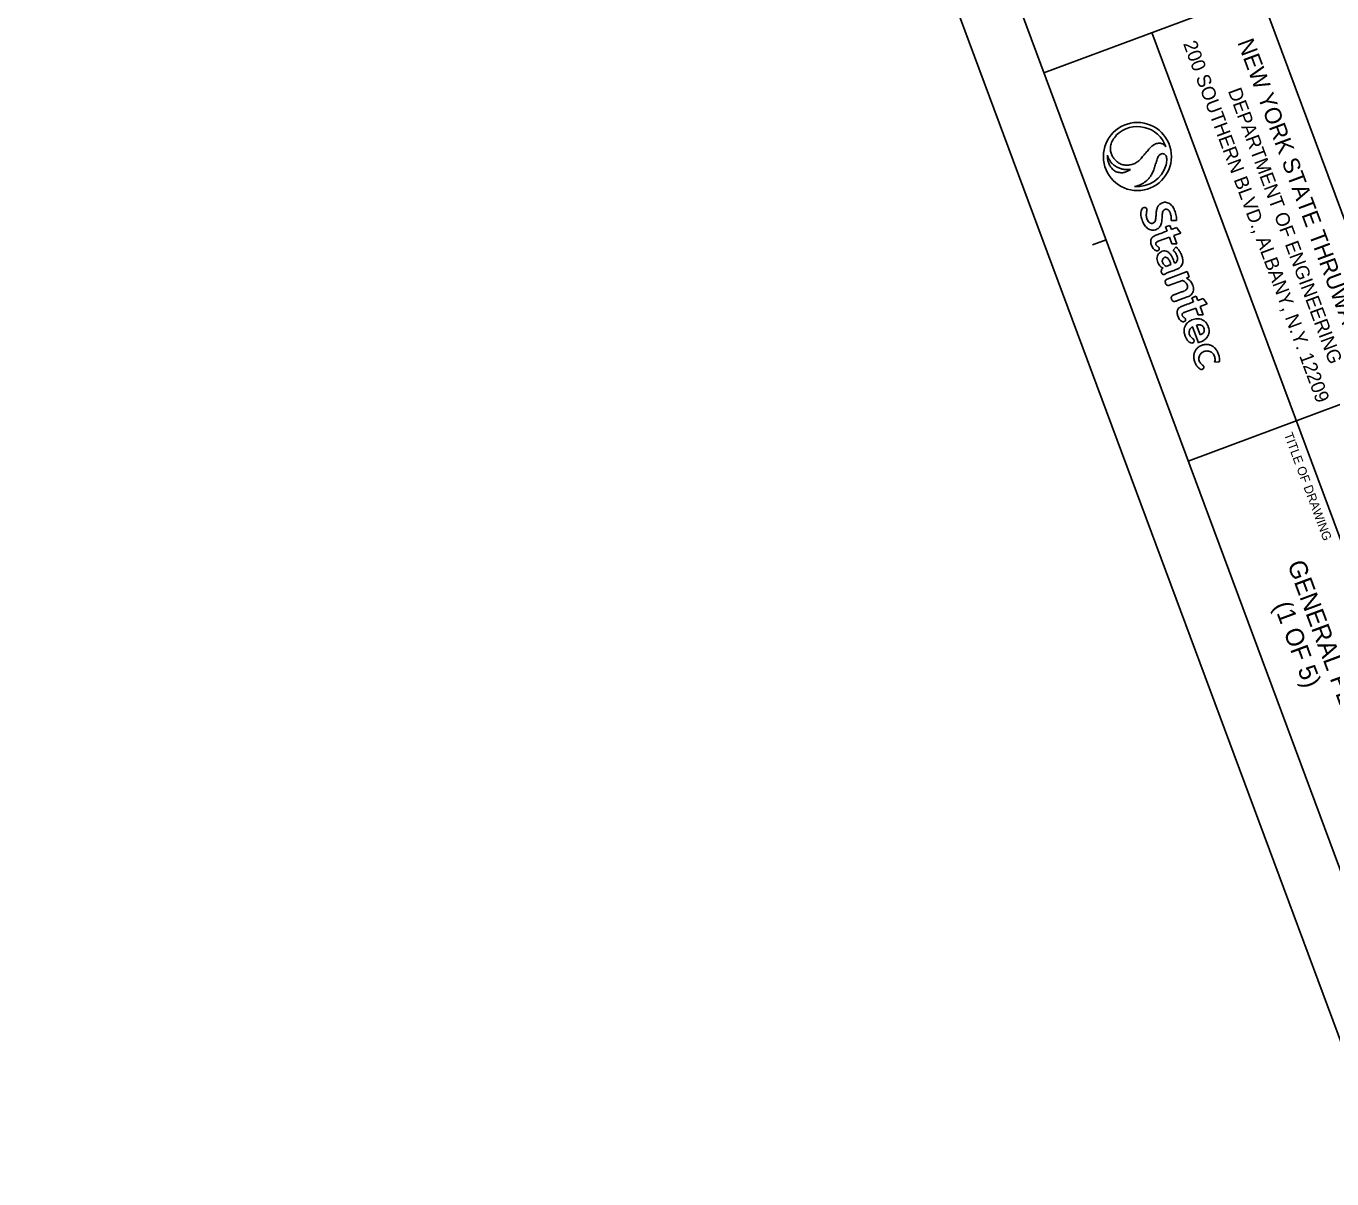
# Model space of a CAD drawing. Extents: x 1040172 to 1040822, y 1127790 to 1128580.
# Drawn here: x 1040172.1 to 1040398.7, y 1127789.6 to 1127989.6 of the extents above; entities that cross this region are included whole.
import ezdxf

# ---------------------------------------------------------------- set-up
doc = ezdxf.new("R2010")
doc.units = 0
for name, color, linetype in [('clip boundary', 7, 'Continuous'), ('G-ANNO-LOGO', 7, 'Continuous'), ('O_Details_Text Title and Subtitle Proposed_P_T', 7, 'Continuous'), ('SHEET_BORDER', 7, 'Continuous'), ('SHEET_BORDER_CUT', 7, 'Continuous')]:
    doc.layers.add(name, color=color, linetype=linetype)

msp = doc.modelspace()

# ---------------------------------------------------------------- linework, layer by layer
at = {"layer": 'clip boundary'}
msp.add_lwpolyline([(1040584.48, 1128580.33), (1040821.52, 1127942.99), (1040409.12, 1127789.61), (1040172.08, 1128426.95)], close=True, dxfattribs=at)
at = {"layer": 'G-ANNO-LOGO'}
for p, q in [((1040370.61, 1127955.06), (1040369.85, 1127954.78)), ((1040369.85, 1127954.78), (1040370.11, 1127954.08)), ((1040370.87, 1127954.37), (1040370.61, 1127955.06)), ((1040370.85, 1127955.9), (1040371.72, 1127955.92)), ((1040371.77, 1127954.7), (1040370.87, 1127954.37)), ((1040372.48, 1127953.73), (1040371.77, 1127954.7)), ((1040368.59, 1127952.3), (1040370.51, 1127953)), ((1040370.51, 1127953), (1040370.94, 1127951.85)), ((1040371.27, 1127953.28), (1040372.48, 1127953.73)), ((1040371.8, 1127951.87), (1040371.27, 1127953.28)), ((1040370.94, 1127951.85), (1040371.8, 1127951.87)), ((1040371.69, 1127951.31), (1040371.17, 1127950.74)), ((1040370.79, 1127948.27), (1040369.93, 1127947.95)), ((1040373.6, 1127947.03), (1040370.12, 1127945.74)), ((1040370.52, 1127944.67), (1040372.81, 1127945.52)), ((1040373.5, 1127945.88), (1040373.94, 1127946.11)), ((1040373.94, 1127946.11), (1040373.6, 1127947.03)), ((1040375.19, 1127942.75), (1040374.43, 1127942.47)), ((1040374.43, 1127942.47), (1040374.69, 1127941.77)), ((1040375.45, 1127942.05), (1040375.19, 1127942.75)), ((1040376.35, 1127942.39), (1040375.45, 1127942.05)), ((1040375.85, 1127940.97), (1040377.06, 1127941.42)), ((1040376.38, 1127939.56), (1040375.85, 1127940.97)), ((1040377.06, 1127941.42), (1040376.35, 1127942.39)), ((1040373.17, 1127939.99), (1040375.09, 1127940.69)), ((1040375.09, 1127940.69), (1040375.52, 1127939.54)), ((1040375.52, 1127939.54), (1040376.38, 1127939.56)), ((1040374.55, 1127937.47), (1040375.58, 1127934.7)), ((1040375.84, 1127936.05), (1040375.22, 1127937.72)), ((1040378.36, 1127931.34), (1040379.16, 1127931.37))]:
    msp.add_line(p, q, dxfattribs=at)
for points in [[(1040369.88, 1127968.71), (1040369.88, 1127968.71)], [(1040369.97, 1127965.55), (1040369.96, 1127965.55)]]:
    msp.add_lwpolyline(points, dxfattribs=at)
msp.add_circle((1040364.96, 1127967), 5.91, dxfattribs=at)
for start, end in [(19.1677, 134.0856), (19.1612, 19.1677), (177.5195, 181.8591), (264.1826, 343.8337)]:
    msp.add_arc((1040364.96, 1127967), 5.21, start, end, dxfattribs=at)
for points, degree in [([(1040369.88, 1127968.71), (1040369.81, 1127968.82), (1040369.65, 1127969.07), (1040369.15, 1127969.3), (1040368.44, 1127969.34), (1040367.77, 1127969.05), (1040367.2, 1127968.56), (1040366.7, 1127967.96), (1040366.13, 1127967.32), (1040365.62, 1127966.66), (1040365.05, 1127966.12), (1040364.37, 1127965.7), (1040363.59, 1127965.52), (1040362.84, 1127965.48), (1040362.07, 1127965.67), (1040361.43, 1127966.06), (1040360.96, 1127966.53), (1040360.61, 1127966.99), (1040360.39, 1127967.57), (1040360.24, 1127968.24), (1040360.3, 1127968.98), (1040360.62, 1127969.87), (1040361.06, 1127970.4), (1040361.34, 1127970.74)], 3), ([(1040369.88, 1127968.71), (1040369.88, 1127968.71), (1040369.88, 1127968.71), (1040369.88, 1127968.71)], 2), ([(1040359.76, 1127967.22), (1040359.8, 1127967.1), (1040359.87, 1127966.81), (1040360.15, 1127966.36), (1040360.47, 1127965.86), (1040360.94, 1127965.48), (1040361.42, 1127965.15), (1040362.03, 1127964.9), (1040362.66, 1127964.74), (1040363.26, 1127964.71), (1040363.6, 1127964.76), (1040363.76, 1127964.78)], 3), ([(1040363.76, 1127964.78), (1040363.64, 1127964.7), (1040363.36, 1127964.49), (1040362.84, 1127964.27), (1040362.23, 1127964.15), (1040361.6, 1127964.25), (1040360.97, 1127964.47), (1040360.49, 1127964.95), (1040360.12, 1127965.51), (1040359.88, 1127966.14), (1040359.8, 1127966.61), (1040359.76, 1127966.83)], 3), ([(1040364.44, 1127961.82), (1040364.62, 1127961.84), (1040364.97, 1127961.89), (1040365.48, 1127962.09), (1040365.92, 1127962.31), (1040366.29, 1127962.6), (1040366.72, 1127962.94), (1040367.14, 1127963.41), (1040367.49, 1127963.99), (1040367.83, 1127964.7), (1040368.05, 1127965.51), (1040368.35, 1127966.37), (1040368.55, 1127967.05), (1040368.95, 1127967.41), (1040369.3, 1127967.54), (1040369.61, 1127967.46), (1040369.86, 1127967.29), (1040370.01, 1127966.99), (1040370.07, 1127966.59), (1040370.05, 1127966.1), (1040370, 1127965.74), (1040369.97, 1127965.55)], 3), ([(1040371.72, 1127955.92), (1040371.73, 1127955.97), (1040371.75, 1127956.23), (1040371.71, 1127956.68), (1040371.58, 1127957.21), (1040371.43, 1127957.67), (1040371.25, 1127958.04), (1040371.04, 1127958.38), (1040370.77, 1127958.68), (1040370.41, 1127958.93), (1040370.01, 1127959.06), (1040369.64, 1127959.08), (1040369.34, 1127959), (1040369.07, 1127958.89), (1040368.84, 1127958.73), (1040368.66, 1127958.54), (1040368.52, 1127958.34), (1040368.41, 1127958.11), (1040368.32, 1127957.85), (1040368.26, 1127957.55), (1040368.22, 1127957.19), (1040368.19, 1127956.8), (1040368.17, 1127956.4), (1040368.13, 1127956.07), (1040368.03, 1127955.79), (1040367.92, 1127955.59), (1040367.74, 1127955.46), (1040367.54, 1127955.4), (1040367.3, 1127955.4), (1040367.06, 1127955.51), (1040366.83, 1127955.74), (1040366.66, 1127956.06), (1040366.54, 1127956.43), (1040366.49, 1127956.78), (1040366.52, 1127957.09), (1040366.53, 1127957.34), (1040366.61, 1127957.53), (1040366.61, 1127957.69), (1040366.62, 1127957.83), (1040366.56, 1127957.96), (1040366.47, 1127958.08), (1040366.33, 1127958.16), (1040366.16, 1127958.18), (1040366, 1127958.13), (1040365.86, 1127958.05), (1040365.74, 1127957.87), (1040365.59, 1127957.55), (1040365.55, 1127957.07), (1040365.6, 1127956.51), (1040365.76, 1127955.99), (1040365.94, 1127955.55), (1040366.13, 1127955.18), (1040366.36, 1127954.88), (1040366.66, 1127954.58), (1040367.05, 1127954.34), (1040367.48, 1127954.2), (1040367.91, 1127954.24), (1040368.27, 1127954.35), (1040368.57, 1127954.51), (1040368.78, 1127954.74), (1040368.98, 1127954.98), (1040369.1, 1127955.33), (1040369.19, 1127955.7), (1040369.22, 1127956.09), (1040369.26, 1127956.51), (1040369.28, 1127956.95), (1040369.33, 1127957.33), (1040369.44, 1127957.61), (1040369.6, 1127957.77), (1040369.79, 1127957.86), (1040369.99, 1127957.87), (1040370.19, 1127957.81), (1040370.37, 1127957.68), (1040370.53, 1127957.49), (1040370.65, 1127957.22), (1040370.74, 1127956.96), (1040370.8, 1127956.68), (1040370.84, 1127956.4), (1040370.85, 1127956.14), (1040370.85, 1127955.97), (1040370.85, 1127955.9)], 3), ([(1040370.11, 1127954.08), (1040369.44, 1127953.83), (1040368.72, 1127953.57), (1040367.93, 1127953.26), (1040367.75, 1127953.16), (1040367.52, 1127952.98), (1040367.39, 1127952.77), (1040367.31, 1127952.57), (1040367.26, 1127952.37), (1040367.27, 1127952.08), (1040367.36, 1127951.72), (1040367.51, 1127951.37), (1040367.69, 1127951.03), (1040367.93, 1127950.8), (1040368.17, 1127950.66), (1040368.39, 1127950.64), (1040368.56, 1127950.69), (1040368.69, 1127950.77), (1040368.74, 1127950.87), (1040368.76, 1127950.98), (1040368.74, 1127951.09), (1040368.7, 1127951.2), (1040368.63, 1127951.3), (1040368.52, 1127951.36), (1040368.4, 1127951.44), (1040368.29, 1127951.56), (1040368.19, 1127951.68), (1040368.15, 1127951.84), (1040368.17, 1127951.99), (1040368.24, 1127952.13), (1040368.39, 1127952.23), (1040368.51, 1127952.28), (1040368.59, 1127952.3)], 3), ([(1040371.43, 1127948.51), (1040371.41, 1127948.58), (1040371.32, 1127948.81), (1040371.15, 1127949.19), (1040370.95, 1127949.65), (1040370.69, 1127950.06), (1040370.37, 1127950.4), (1040369.94, 1127950.64), (1040369.45, 1127950.65), (1040369.05, 1127950.47), (1040368.72, 1127950.28), (1040368.51, 1127949.96), (1040368.35, 1127949.55), (1040368.35, 1127949.05), (1040368.52, 1127948.59), (1040368.73, 1127948.19), (1040368.96, 1127947.91), (1040369.21, 1127947.74), (1040369.35, 1127947.68), (1040369.43, 1127947.64)], 3), ([(1040369.43, 1127947.64), (1040369.4, 1127947.62), (1040369.31, 1127947.58), (1040369.21, 1127947.44), (1040369.11, 1127947.26), (1040369.09, 1127946.99), (1040369.19, 1127946.75), (1040369.32, 1127946.54), (1040369.54, 1127946.52), (1040369.72, 1127946.58), (1040369.94, 1127946.72), (1040370.59, 1127947.03), (1040371.31, 1127947.24), (1040372.06, 1127947.54), (1040372.4, 1127947.77), (1040372.65, 1127948.1), (1040372.83, 1127948.41), (1040372.88, 1127948.85), (1040372.82, 1127949.35), (1040372.66, 1127949.9), (1040372.4, 1127950.43), (1040372.08, 1127950.91), (1040371.82, 1127951.18), (1040371.69, 1127951.31)], 3), ([(1040371.17, 1127950.74), (1040371.22, 1127950.7), (1040371.35, 1127950.58), (1040371.52, 1127950.36), (1040371.71, 1127950.09), (1040371.83, 1127949.82), (1040371.93, 1127949.52), (1040371.95, 1127949.22), (1040371.9, 1127948.94), (1040371.77, 1127948.71), (1040371.6, 1127948.57), (1040371.47, 1127948.52), (1040371.43, 1127948.51)], 3), ([(1040369.93, 1127947.95), (1040369.9, 1127947.97), (1040369.79, 1127948.04), (1040369.62, 1127948.19), (1040369.42, 1127948.4), (1040369.3, 1127948.67), (1040369.27, 1127948.93), (1040369.32, 1127949.14), (1040369.4, 1127949.3), (1040369.53, 1127949.42), (1040369.69, 1127949.5), (1040369.86, 1127949.53), (1040370.06, 1127949.49), (1040370.22, 1127949.36), (1040370.38, 1127949.19), (1040370.51, 1127948.94), (1040370.63, 1127948.68), (1040370.73, 1127948.44), (1040370.78, 1127948.32), (1040370.79, 1127948.27)], 3), ([(1040370.12, 1127945.74), (1040370.08, 1127945.71), (1040369.98, 1127945.65), (1040369.84, 1127945.51), (1040369.76, 1127945.26), (1040369.86, 1127944.98), (1040369.98, 1127944.72), (1040370.22, 1127944.62), (1040370.4, 1127944.62), (1040370.48, 1127944.66), (1040370.52, 1127944.67)], 3), ([(1040372.81, 1127945.52), (1040372.83, 1127945.51), (1040372.93, 1127945.46), (1040373.1, 1127945.32), (1040373.34, 1127945.15), (1040373.54, 1127944.89), (1040373.65, 1127944.59), (1040373.67, 1127944.27), (1040373.53, 1127943.99), (1040373.33, 1127943.79), (1040373.02, 1127943.62), (1040372.51, 1127943.47), (1040371.89, 1127943.21), (1040371.36, 1127943.05), (1040371, 1127942.89), (1040370.86, 1127942.69), (1040370.8, 1127942.43), (1040370.9, 1127942.18), (1040371.05, 1127941.96), (1040371.27, 1127941.82), (1040371.57, 1127941.86), (1040372.06, 1127942.1), (1040372.69, 1127942.3), (1040373.37, 1127942.57), (1040373.82, 1127942.7), (1040374.17, 1127942.9), (1040374.39, 1127943.12), (1040374.59, 1127943.41), (1040374.69, 1127943.79), (1040374.73, 1127944.24), (1040374.58, 1127944.68), (1040374.41, 1127945.06), (1040374.17, 1127945.37), (1040373.91, 1127945.63), (1040373.66, 1127945.77), (1040373.54, 1127945.85), (1040373.5, 1127945.88)], 3), ([(1040374.69, 1127941.77), (1040374.01, 1127941.52), (1040373.3, 1127941.25), (1040372.51, 1127940.95), (1040372.33, 1127940.84), (1040372.09, 1127940.67), (1040371.97, 1127940.46), (1040371.89, 1127940.26), (1040371.84, 1127940.06), (1040371.85, 1127939.77), (1040371.94, 1127939.41), (1040372.09, 1127939.06), (1040372.27, 1127938.71), (1040372.51, 1127938.49), (1040372.75, 1127938.35), (1040372.97, 1127938.33), (1040373.14, 1127938.38), (1040373.27, 1127938.46), (1040373.32, 1127938.56), (1040373.34, 1127938.67), (1040373.32, 1127938.78), (1040373.28, 1127938.88), (1040373.21, 1127938.98), (1040373.1, 1127939.05), (1040372.98, 1127939.13), (1040372.87, 1127939.24), (1040372.77, 1127939.37), (1040372.73, 1127939.52), (1040372.75, 1127939.68), (1040372.81, 1127939.82), (1040372.97, 1127939.92), (1040373.09, 1127939.97), (1040373.17, 1127939.99)], 3), ([(1040375.58, 1127934.7), (1040375.69, 1127934.74), (1040375.95, 1127934.83), (1040376.36, 1127935.03), (1040376.8, 1127935.32), (1040377.08, 1127935.68), (1040377.31, 1127936.06), (1040377.41, 1127936.48), (1040377.42, 1127936.95), (1040377.28, 1127937.43), (1040377.1, 1127937.89), (1040376.8, 1127938.28), (1040376.44, 1127938.57), (1040376.01, 1127938.78), (1040375.56, 1127938.86), (1040375.1, 1127938.83), (1040374.66, 1127938.73), (1040374.2, 1127938.56), (1040373.82, 1127938.31), (1040373.48, 1127937.99), (1040373.22, 1127937.61), (1040373.09, 1127937.12), (1040373.03, 1127936.55), (1040373.21, 1127935.98), (1040373.4, 1127935.48), (1040373.65, 1127935.08), (1040373.94, 1127934.8), (1040374.25, 1127934.64), (1040374.52, 1127934.63), (1040374.69, 1127934.74), (1040374.8, 1127934.89), (1040374.79, 1127935.06), (1040374.76, 1127935.21), (1040374.64, 1127935.36), (1040374.44, 1127935.52), (1040374.21, 1127935.69), (1040374.05, 1127935.95), (1040373.94, 1127936.21), (1040373.91, 1127936.49), (1040373.98, 1127936.76), (1040374.07, 1127937.04), (1040374.26, 1127937.25), (1040374.42, 1127937.39), (1040374.52, 1127937.45), (1040374.55, 1127937.47)], 3), ([(1040375.22, 1127937.72), (1040375.25, 1127937.73), (1040375.34, 1127937.76), (1040375.5, 1127937.81), (1040375.73, 1127937.83), (1040376, 1127937.78), (1040376.25, 1127937.65), (1040376.45, 1127937.41), (1040376.57, 1127937.12), (1040376.59, 1127936.81), (1040376.52, 1127936.52), (1040376.31, 1127936.31), (1040376.08, 1127936.16), (1040375.91, 1127936.08), (1040375.84, 1127936.05)], 3), ([(1040379.16, 1127931.37), (1040379.18, 1127931.48), (1040379.22, 1127931.75), (1040379.17, 1127932.24), (1040379.02, 1127932.81), (1040378.74, 1127933.37), (1040378.35, 1127933.86), (1040377.87, 1127934.21), (1040377.32, 1127934.39), (1040376.76, 1127934.41), (1040376.19, 1127934.29), (1040375.66, 1127934.04), (1040375.24, 1127933.67), (1040374.96, 1127933.25), (1040374.78, 1127932.74), (1040374.73, 1127932.12), (1040374.86, 1127931.47), (1040375.11, 1127930.92), (1040375.41, 1127930.49), (1040375.72, 1127930.18), (1040376.04, 1127930.03), (1040376.27, 1127930.1), (1040376.43, 1127930.18), (1040376.48, 1127930.33), (1040376.51, 1127930.47), (1040376.47, 1127930.6), (1040376.38, 1127930.76), (1040376.19, 1127930.86), (1040376.02, 1127931.05), (1040375.83, 1127931.23), (1040375.69, 1127931.54), (1040375.6, 1127931.88), (1040375.65, 1127932.26), (1040375.8, 1127932.58), (1040376.02, 1127932.88), (1040376.34, 1127933.07), (1040376.65, 1127933.24), (1040377.02, 1127933.27), (1040377.37, 1127933.25), (1040377.68, 1127933.15), (1040377.96, 1127932.97), (1040378.18, 1127932.72), (1040378.33, 1127932.39), (1040378.43, 1127932.04), (1040378.45, 1127931.67), (1040378.39, 1127931.45), (1040378.36, 1127931.34)], 3)]:
    msp.add_open_spline(points, degree=degree, dxfattribs=at)
at = {"layer": 'SHEET_BORDER'}
for p, q in [((1040447.57, 1127830.58), (1040330.5, 1128145.33)), ((1040386.24, 1127995.48), (1040348.74, 1127981.54)), ((1040417.6, 1127853.77), (1040367.49, 1127988.51)), ((1040359.53, 1127952.54), (1040357.19, 1127951.67)), ((1040411.29, 1127928.11), (1040373.8, 1127914.17))]:
    msp.add_line(p, q, dxfattribs=at)
msp.add_lwpolyline([(1040412.42, 1127817.51), (1040409.2, 1127818.98), (1040191.33, 1128404.77), (1040192.81, 1128407.99), (1040581.19, 1128552.44), (1040584.4, 1128550.96), (1040802.27, 1127965.17), (1040800.8, 1127961.95)], close=True, dxfattribs=at)
at = {"layer": 'SHEET_BORDER_CUT'}
msp.add_lwpolyline([(1040172.08, 1128426.95), (1040409.12, 1127789.61), (1040821.52, 1127942.99), (1040584.48, 1128580.33)], close=True, dxfattribs=at)

# ---------------------------------------------------------------- texts
at = {"layer": 'O_Details_Text Title and Subtitle Proposed_P_T'}
for s, height, p in [('GENERAL PLAN', 3.1248, (1040390.95, 1127896.28)), ('(1 OF 5)', 3.125, (1040388.6, 1127889.14))]:
    msp.add_text(s, height=height, rotation=290.4011, dxfattribs=at).set_placement(p)
at = {"layer": 'SHEET_BORDER'}
for s, height, p in [('200 SOUTHERN BLVD., ALBANY, N.Y. 12209', 2.4, (1040372.87, 1127986.59)), ('NEW YORK STATE THRUWAY AUTHORITY', 2.88, (1040382.28, 1127986.82)), ('DEPARTMENT OF ENGINEERING', 2.4, (1040380.64, 1127978.4)), ('TITLE OF DRAWING', 1.5625, (1040390.37, 1127918.79))]:
    msp.add_text(s, height=height, rotation=290.4011, dxfattribs=at).set_placement(p)

doc.saveas('drawing.dxf')
